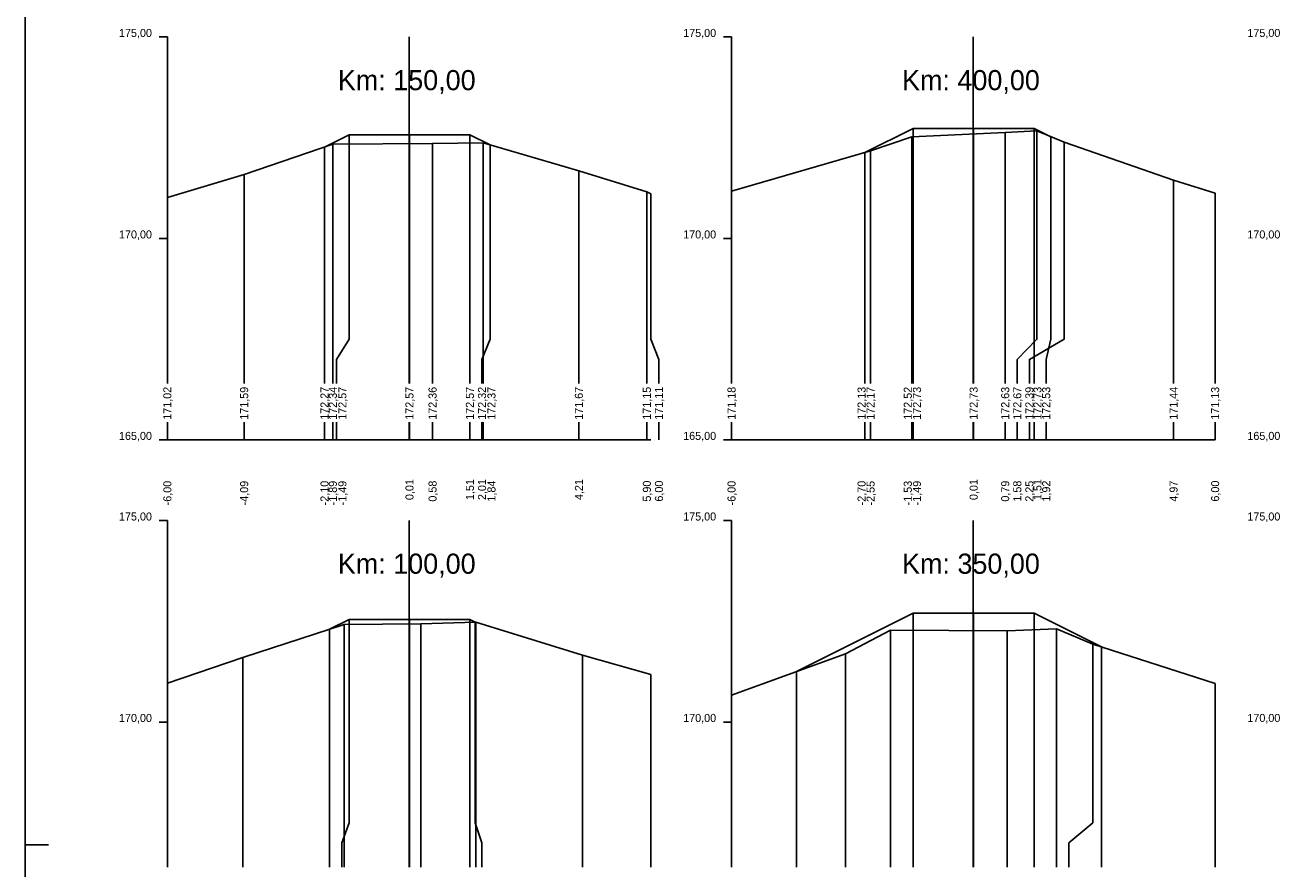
# Model space of a CAD drawing. Extents: x -614174 to -599765, y -1185887 to -1181080.
# Drawn here: x -601084.96 to -601053.82, y -1184419.99 to -1184399.05 of the extents above; entities that cross this region are included whole.
import ezdxf

# ---------------------------------------------------------------- set-up
doc = ezdxf.new("R2010")
doc.units = 0
for name, color, linetype in [('11', 7, 'Continuous'), ('16', 7, 'Continuous'), ('21', 7, 'Continuous'), ('28', 7, 'Continuous'), ('59', 7, 'Continuous'), ('8', 7, 'Continuous'), ('návrh', 7, 'Continuous')]:
    doc.layers.add(name, color=color, linetype=linetype)

msp = doc.modelspace()

# ---------------------------------------------------------------- linework, layer by layer
for points in [[(-601077.527, -1184402.073), (-601076.919, -1184401.77), (-601075.419, -1184401.77), (-601073.919, -1184401.77), (-601073.419, -1184402.019)], [(-601076.919, -1184401.77), (-601076.919, -1184401.77), (-601076.919, -1184401.77)], [(-601075.419, -1184401.77), (-601075.419, -1184401.77), (-601075.419, -1184401.77)], [(-601073.919, -1184401.77), (-601073.919, -1184401.77), (-601073.919, -1184401.77)], [(-601067.427, -1184403.165), (-601063.976, -1184402.168), (-601062.955, -1184401.818), (-601060.636, -1184401.714), (-601059.848, -1184401.674), (-601059.174, -1184401.953), (-601056.458, -1184402.898), (-601055.427, -1184403.215)], [(-601064.123, -1184402.211), (-601062.919, -1184401.609), (-601061.419, -1184401.609), (-601059.919, -1184401.609), (-601059.506, -1184401.816)], [(-601062.919, -1184401.609), (-601062.919, -1184401.609), (-601062.919, -1184401.609)], [(-601061.419, -1184401.609), (-601061.419, -1184401.609), (-601061.419, -1184401.609)], [(-601059.919, -1184401.609), (-601059.919, -1184401.609), (-601059.919, -1184401.609)], [(-601081.427, -1184403.324), (-601079.521, -1184402.757), (-601077.32, -1184402.002), (-601074.846, -1184401.984), (-601073.589, -1184401.97), (-601071.214, -1184402.667), (-601069.528, -1184403.187), (-601069.427, -1184403.236)], [(-601077.526, -1184402.073), (-601077.527, -1184402.073), (-601077.527, -1184402.073)], [(-601064.123, -1184402.211), (-601064.123, -1184402.211), (-601064.123, -1184402.211)], [(-601065.818, -1184415.09), (-601062.919, -1184413.641), (-601061.419, -1184413.641), (-601059.919, -1184413.641), (-601058.246, -1184414.478)], [(-601062.919, -1184413.641), (-601062.919, -1184413.641), (-601062.919, -1184413.641)], [(-601061.419, -1184413.641), (-601061.419, -1184413.641), (-601061.419, -1184413.641)], [(-601059.919, -1184413.641), (-601059.919, -1184413.641), (-601059.919, -1184413.641)], [(-601081.427, -1184415.381), (-601079.557, -1184414.739), (-601077.039, -1184413.925), (-601075.135, -1184413.902), (-601073.774, -1184413.867), (-601071.126, -1184414.681), (-601069.427, -1184415.162)], [(-601077.4, -1184414.042), (-601076.919, -1184413.802), (-601075.419, -1184413.802), (-601073.919, -1184413.802), (-601073.788, -1184413.867)], [(-601076.919, -1184413.802), (-601076.919, -1184413.802), (-601076.919, -1184413.802)], [(-601075.419, -1184413.802), (-601075.419, -1184413.802), (-601075.419, -1184413.802)], [(-601073.919, -1184413.802), (-601073.919, -1184413.802), (-601073.919, -1184413.802)], [(-601077.4, -1184414.042), (-601077.4, -1184414.042), (-601077.399, -1184414.042)], [(-601067.427, -1184415.675), (-601064.597, -1184414.647), (-601063.482, -1184414.066), (-601060.587, -1184414.081), (-601059.361, -1184414.029), (-601058.459, -1184414.409), (-601055.427, -1184415.385)], [(-601065.82, -1184415.091), (-601065.818, -1184415.09), (-601065.817, -1184415.09)]]:
    msp.add_lwpolyline(points)
at = {"layer": '11'}
for points in [[(-601076.919, -1184401.77), (-601076.919, -1184406.842), (-601077.227, -1184407.342), (-601077.227, -1184407.944)], [(-601075.419, -1184401.77), (-601075.419, -1184406.842), (-601075.419, -1184407.342), (-601075.419, -1184407.944)], [(-601073.919, -1184401.77), (-601073.919, -1184406.842), (-601073.919, -1184407.342), (-601073.919, -1184407.944)], [(-601062.955, -1184401.818), (-601062.955, -1184406.842), (-601062.955, -1184407.342), (-601062.955, -1184407.944)], [(-601062.919, -1184401.609), (-601062.919, -1184406.842), (-601062.919, -1184407.342), (-601062.919, -1184407.944)], [(-601061.419, -1184401.609), (-601061.419, -1184406.842), (-601061.419, -1184407.342), (-601061.419, -1184407.944)], [(-601060.636, -1184401.714), (-601060.636, -1184406.842), (-601060.636, -1184407.342), (-601060.636, -1184407.944)], [(-601059.848, -1184401.674), (-601059.848, -1184406.842), (-601060.336, -1184407.342), (-601060.336, -1184407.944)], [(-601059.919, -1184401.609), (-601059.919, -1184406.842), (-601059.919, -1184407.342), (-601059.919, -1184407.944)], [(-601059.506, -1184401.816), (-601059.506, -1184406.842), (-601059.619, -1184407.342), (-601059.619, -1184407.944)], [(-601077.527, -1184402.073), (-601077.527, -1184406.842), (-601077.527, -1184407.342), (-601077.527, -1184407.944)], [(-601077.32, -1184402.002), (-601077.32, -1184406.842), (-601077.32, -1184407.342), (-601077.32, -1184407.944)], [(-601074.846, -1184401.984), (-601074.846, -1184406.842), (-601074.846, -1184407.342), (-601074.846, -1184407.944)], [(-601073.419, -1184402.019), (-601073.419, -1184406.842), (-601073.619, -1184407.342), (-601073.619, -1184407.944)], [(-601073.589, -1184401.97), (-601073.589, -1184406.842), (-601073.589, -1184407.342), (-601073.589, -1184407.944)], [(-601059.174, -1184401.953), (-601059.174, -1184406.842), (-601060.036, -1184407.342), (-601060.036, -1184407.944)], [(-601064.123, -1184402.211), (-601064.123, -1184406.842), (-601064.123, -1184407.342), (-601064.123, -1184407.944)], [(-601063.976, -1184402.168), (-601063.976, -1184406.842), (-601063.976, -1184407.342), (-601063.976, -1184407.944)], [(-601079.521, -1184402.757), (-601079.521, -1184406.842), (-601079.521, -1184407.342), (-601079.521, -1184407.944)], [(-601071.214, -1184402.667), (-601071.214, -1184406.842), (-601071.214, -1184407.342), (-601071.214, -1184407.944)], [(-601056.458, -1184402.898), (-601056.458, -1184406.842), (-601056.458, -1184407.342), (-601056.458, -1184407.944)], [(-601081.427, -1184403.324), (-601081.427, -1184406.842), (-601081.427, -1184407.342), (-601081.427, -1184407.944)], [(-601069.528, -1184403.187), (-601069.528, -1184406.842), (-601069.528, -1184407.342), (-601069.528, -1184407.944)], [(-601069.427, -1184403.236), (-601069.427, -1184406.842), (-601069.228, -1184407.342), (-601069.228, -1184407.944)], [(-601067.427, -1184403.165), (-601067.427, -1184406.842), (-601067.427, -1184407.342), (-601067.427, -1184407.944)], [(-601055.427, -1184403.215), (-601055.427, -1184406.842), (-601055.427, -1184407.342), (-601055.427, -1184407.944)], [(-601081.427, -1184408.902), (-601081.427, -1184409.342)], [(-601079.521, -1184408.902), (-601079.521, -1184409.342)], [(-601077.527, -1184408.902), (-601077.527, -1184409.342)], [(-601077.32, -1184408.902), (-601077.32, -1184409.342)], [(-601077.227, -1184408.902), (-601077.227, -1184409.342)], [(-601075.419, -1184408.902), (-601075.419, -1184409.342)], [(-601074.846, -1184408.902), (-601074.846, -1184409.342)], [(-601073.919, -1184408.902), (-601073.919, -1184409.342)], [(-601073.619, -1184408.902), (-601073.619, -1184409.342)], [(-601073.589, -1184408.902), (-601073.589, -1184409.342)], [(-601071.214, -1184408.902), (-601071.214, -1184409.342)], [(-601069.528, -1184408.902), (-601069.528, -1184409.342)], [(-601069.228, -1184408.902), (-601069.228, -1184409.342)], [(-601067.427, -1184408.902), (-601067.427, -1184409.342)], [(-601064.123, -1184408.902), (-601064.123, -1184409.342)], [(-601063.976, -1184408.902), (-601063.976, -1184409.342)], [(-601062.955, -1184408.902), (-601062.955, -1184409.342)], [(-601062.919, -1184408.902), (-601062.919, -1184409.342)], [(-601061.419, -1184408.902), (-601061.419, -1184409.342)], [(-601060.636, -1184408.902), (-601060.636, -1184409.342)], [(-601060.336, -1184408.902), (-601060.336, -1184409.342)], [(-601060.036, -1184408.902), (-601060.036, -1184409.342)], [(-601059.919, -1184408.902), (-601059.919, -1184409.342)], [(-601059.619, -1184408.902), (-601059.619, -1184409.342)], [(-601056.458, -1184408.902), (-601056.458, -1184409.342)], [(-601055.427, -1184408.902), (-601055.427, -1184409.342)], [(-601062.919, -1184413.641), (-601062.919, -1184418.842), (-601062.919, -1184419.342), (-601062.919, -1184419.944)], [(-601061.419, -1184413.641), (-601061.419, -1184418.842), (-601061.419, -1184419.342), (-601061.419, -1184419.944)], [(-601059.919, -1184413.641), (-601059.919, -1184418.842), (-601059.919, -1184419.342), (-601059.919, -1184419.944)], [(-601076.919, -1184413.802), (-601076.919, -1184418.842), (-601077.1, -1184419.342), (-601077.1, -1184419.944)], [(-601077.039, -1184413.925), (-601077.039, -1184418.842), (-601077.039, -1184419.342), (-601077.039, -1184419.944)], [(-601075.419, -1184413.802), (-601075.419, -1184418.842), (-601075.419, -1184419.342), (-601075.419, -1184419.944)], [(-601075.135, -1184413.902), (-601075.135, -1184418.842), (-601075.135, -1184419.342), (-601075.135, -1184419.944)], [(-601073.919, -1184413.802), (-601073.919, -1184418.842), (-601073.919, -1184419.342), (-601073.919, -1184419.944)], [(-601073.788, -1184413.867), (-601073.788, -1184418.842), (-601073.619, -1184419.342), (-601073.619, -1184419.944)], [(-601073.774, -1184413.867), (-601073.774, -1184418.842), (-601073.774, -1184419.342), (-601073.774, -1184419.944)], [(-601077.4, -1184414.042), (-601077.4, -1184418.842), (-601077.4, -1184419.342), (-601077.4, -1184419.944)], [(-601063.482, -1184414.066), (-601063.482, -1184418.842), (-601063.482, -1184419.342), (-601063.482, -1184419.944)], [(-601060.587, -1184414.081), (-601060.587, -1184418.842), (-601060.587, -1184419.342), (-601060.587, -1184419.944)], [(-601059.361, -1184414.029), (-601059.361, -1184418.842), (-601059.361, -1184419.342), (-601059.361, -1184419.944)], [(-601058.459, -1184414.409), (-601058.459, -1184418.842), (-601059.061, -1184419.342), (-601059.061, -1184419.944)], [(-601058.246, -1184414.478), (-601058.246, -1184418.842), (-601058.246, -1184419.342), (-601058.246, -1184419.944)], [(-601079.557, -1184414.739), (-601079.557, -1184418.842), (-601079.557, -1184419.342), (-601079.557, -1184419.944)], [(-601071.126, -1184414.681), (-601071.126, -1184418.842), (-601071.126, -1184419.342), (-601071.126, -1184419.944)], [(-601064.597, -1184414.647), (-601064.597, -1184418.842), (-601064.597, -1184419.342), (-601064.597, -1184419.944)], [(-601069.427, -1184415.162), (-601069.427, -1184418.842), (-601069.427, -1184419.342), (-601069.427, -1184419.944)], [(-601065.818, -1184415.09), (-601065.818, -1184418.842), (-601065.818, -1184419.342), (-601065.818, -1184419.944)], [(-601081.427, -1184415.381), (-601081.427, -1184418.842), (-601081.427, -1184419.342), (-601081.427, -1184419.944)], [(-601055.427, -1184415.385), (-601055.427, -1184418.842), (-601055.427, -1184419.342), (-601055.427, -1184419.944)], [(-601067.427, -1184415.675), (-601067.427, -1184418.842), (-601067.427, -1184419.342), (-601067.427, -1184419.944)]]:
    msp.add_lwpolyline(points, dxfattribs=at)
at = {"layer": '16'}
for p, q in [((-601081.427, -1184409.342), (-601069.427, -1184409.342)), ((-601067.427, -1184409.342), (-601055.427, -1184409.342))]:
    msp.add_line(p, q, dxfattribs=at)
for points in [[(-601059.506, -1184401.816), (-601059.506, -1184401.816), (-601059.506, -1184401.815)], [(-601073.42, -1184402.019), (-601073.419, -1184402.019), (-601073.419, -1184402.02)], [(-601073.788, -1184413.867), (-601073.788, -1184413.867), (-601073.788, -1184413.867)], [(-601058.246, -1184414.477), (-601058.246, -1184414.478), (-601058.246, -1184414.478)]]:
    msp.add_lwpolyline(points, dxfattribs=at)
at = {"layer": '21'}
for p, q in [((-601081.627, -1184399.342), (-601081.427, -1184399.342)), ((-601067.627, -1184399.342), (-601067.427, -1184399.342)), ((-601081.627, -1184404.342), (-601081.427, -1184404.342)), ((-601067.627, -1184404.342), (-601067.427, -1184404.342)), ((-601081.627, -1184409.342), (-601081.427, -1184409.342)), ((-601067.627, -1184409.342), (-601067.427, -1184409.342)), ((-601081.627, -1184411.342), (-601081.427, -1184411.342)), ((-601067.627, -1184411.342), (-601067.427, -1184411.342)), ((-601081.627, -1184416.342), (-601081.427, -1184416.342)), ((-601067.627, -1184416.342), (-601067.427, -1184416.342))]:
    msp.add_line(p, q, dxfattribs=at)
at = {"layer": '28'}
for p, q in [((-601075.427, -1184407.944), (-601075.427, -1184399.342)), ((-601061.427, -1184407.944), (-601061.427, -1184399.342)), ((-601075.427, -1184409.342), (-601075.427, -1184408.902)), ((-601061.427, -1184409.342), (-601061.427, -1184408.902)), ((-601075.427, -1184419.944), (-601075.427, -1184411.342)), ((-601061.427, -1184419.944), (-601061.427, -1184411.342))]:
    msp.add_line(p, q, dxfattribs=at)
at = {"layer": '8'}
for p, q in [((-601081.427, -1184407.944), (-601081.427, -1184399.342)), ((-601067.427, -1184407.944), (-601067.427, -1184399.342)), ((-601081.427, -1184409.342), (-601081.427, -1184408.902)), ((-601067.427, -1184409.342), (-601067.427, -1184408.902)), ((-601081.427, -1184419.944), (-601081.427, -1184411.342)), ((-601067.427, -1184419.944), (-601067.427, -1184411.342))]:
    msp.add_line(p, q, dxfattribs=at)
at = {"layer": 'návrh'}
for p, q in [((-601084.957, -1184419.39), (-601084.957, -1184389.69)), ((-601084.957, -1184449.09), (-601084.957, -1184419.39)), ((-601084.957, -1184419.39), (-601084.373, -1184419.39))]:
    msp.add_line(p, q, dxfattribs=at)

# ---------------------------------------------------------------- texts
at = {"layer": '16'}
for s, p in [('171,02', (-601081.327, -1184408.842)), ('171,59', (-601079.421, -1184408.842)), ('172,27', (-601077.427, -1184408.842)), ('172,34', (-601077.22, -1184408.842)), ('172,57', (-601076.984, -1184408.842)), ('172,57', (-601075.319, -1184408.842)), ('172,36', (-601074.746, -1184408.842)), ('172,57', (-601073.819, -1184408.842)), ('172,32', (-601073.519, -1184408.842)), ('172,37', (-601073.284, -1184408.842)), ('171,67', (-601071.114, -1184408.842)), ('171,15', (-601069.428, -1184408.842)), ('171,11', (-601069.128, -1184408.842)), ('171,18', (-601067.327, -1184408.842)), ('172,13', (-601064.1, -1184408.842)), ('172,17', (-601063.876, -1184408.842)), ('172,52', (-601062.953, -1184408.842)), ('172,73', (-601062.726, -1184408.842)), ('172,73', (-601061.319, -1184408.842)), ('172,63', (-601060.536, -1184408.842)), ('172,67', (-601060.236, -1184408.842)), ('172,39', (-601059.936, -1184408.842)), ('172,73', (-601059.736, -1184408.842)), ('172,53', (-601059.519, -1184408.842)), ('171,44', (-601056.358, -1184408.842)), ('171,13', (-601055.327, -1184408.842))]:
    msp.add_text(s, height=0.2, rotation=90, dxfattribs=at).set_placement(p)
at = {"layer": '21'}
for s, p in [('175,00', (-601082.627, -1184399.342)), ('175,00', (-601068.627, -1184399.342)), ('175,00', (-601054.627, -1184399.342)), ('170,00', (-601082.627, -1184404.342)), ('170,00', (-601068.627, -1184404.342)), ('170,00', (-601054.627, -1184404.342)), ('165,00', (-601082.627, -1184409.342)), ('165,00', (-601068.627, -1184409.342)), ('165,00', (-601054.627, -1184409.342)), ('175,00', (-601082.627, -1184411.342)), ('175,00', (-601068.627, -1184411.342)), ('175,00', (-601054.627, -1184411.342)), ('170,00', (-601082.627, -1184416.342)), ('170,00', (-601068.627, -1184416.342)), ('170,00', (-601054.627, -1184416.342))]:
    msp.add_text(s, height=0.2, dxfattribs=at).set_placement(p)
at = {"layer": '28'}
for s, p in [('Km: 150,00', (-601077.196, -1184400.663)), ('Km: 400,00', (-601063.196, -1184400.663)), ('Km: 100,00', (-601077.196, -1184412.663)), ('Km: 350,00', (-601063.196, -1184412.663))]:
    msp.add_text(s, height=0.5, dxfattribs=at).set_placement(p)
at = {"layer": '59'}
for s, p in [('-6,00', (-601081.327, -1184410.965)), ('-4,09', (-601079.421, -1184410.966)), ('-2,10', (-601077.427, -1184410.965)), ('-1,89', (-601077.22, -1184410.966)), ('-1,49', (-601076.984, -1184410.966)), ('0,01', (-601075.319, -1184410.834)), ('0,58', (-601074.746, -1184410.873)), ('1,51', (-601073.819, -1184410.834)), ('2,01', (-601073.519, -1184410.834)), ('1,84', (-601073.284, -1184410.872)), ('4,21', (-601071.114, -1184410.834)), ('5,90', (-601069.428, -1184410.872)), ('6,00', (-601069.128, -1184410.872)), ('-6,00', (-601067.327, -1184410.965)), ('-2,70', (-601064.1, -1184410.965)), ('-2,55', (-601063.876, -1184410.968)), ('-1,53', (-601062.953, -1184410.966)), ('-1,49', (-601062.726, -1184410.966)), ('0,01', (-601061.319, -1184410.834)), ('0,79', (-601060.536, -1184410.873)), ('1,58', (-601060.236, -1184410.873)), ('2,25', (-601059.936, -1184410.875)), ('1,51', (-601059.736, -1184410.834)), ('1,92', (-601059.519, -1184410.871)), ('4,97', (-601056.358, -1184410.873)), ('6,00', (-601055.327, -1184410.872))]:
    msp.add_text(s, height=0.2, rotation=90, dxfattribs=at).set_placement(p)

doc.saveas('drawing.dxf')
